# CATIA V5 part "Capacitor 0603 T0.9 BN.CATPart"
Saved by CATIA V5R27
Part number: Capacitor 0603 T0.9 BN
Definition: Capacitor 0603 T0.9 BN
Nomenclature: Capacitor 0603 T0.9 BN v2
Source: Unknown
Bounding box of the stored display mesh (mm): x -0.85 to 0.85, y -0.45 to 0.45, z 0 to 0.9
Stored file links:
  E:\university\my-thesis\My Thesis Publication\Final-Updata\CAD\Capacitor 0603 T0.9 BN.CATPart
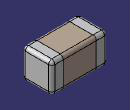
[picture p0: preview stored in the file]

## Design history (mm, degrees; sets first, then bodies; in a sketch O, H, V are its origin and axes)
Body1 "Body1" (main body)
  Solid1: solid without history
